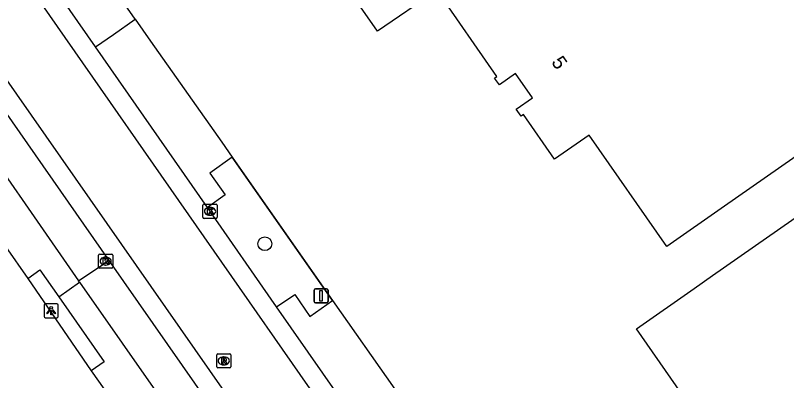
# Model space of a CAD drawing. Extents: x 156651 to 158072, y 387631 to 388990.
# Drawn here: x 157185.4 to 157240.2, y 388242.5 to 388268.5 of the extents above; entities that cross this region are included whole.
import ezdxf

# ---------------------------------------------------------------- set-up
doc = ezdxf.new("R2010")
doc.units = 0
for name, color, linetype in [('IMGEO_Berm_groen', 7, 'Continuous'), ('IMGEO_Boom', 7, 'Continuous'), ('IMGEO_Groenvoorziening', 7, 'Continuous'), ('IMGEO_Hek', 7, 'Continuous'), ('IMGEO_Kolk', 7, 'Continuous'), ('IMGEO_Lichtpunt', 7, 'Continuous'), ('IMGEO_Pand', 7, 'Continuous'), ('IMGEO_Pand_nummerreeks', 7, 'Continuous'), ('IMGEO_Rijbaan_lokaal_gesloten', 7, 'Continuous'), ('IMGEO_Rijbaan_lokaal_open', 7, 'Continuous'), ('IMGEO_Rioolput', 7, 'Continuous'), ('IMGEO_Verkeersbordpaal', 7, 'Continuous'), ('IMGEO_Voetpad_open', 7, 'Continuous')]:
    doc.layers.add(name, color=color, linetype=linetype)

msp = doc.modelspace()

# ---------------------------------------------------------------- linework, layer by layer
at = {"layer": 'IMGEO_Berm_groen'}
for points in [[(157193.882, 388268.245), (157172.367, 388299.009)], [(157207.925, 388248.229), (157200.786, 388258.42)]]:
    msp.add_lwpolyline(points, dxfattribs=at)
at = {"layer": 'IMGEO_Boom'}
msp.add_circle((157203.099, 388252.27), 0.489, dxfattribs=at)
at = {"layer": 'IMGEO_Groenvoorziening'}
msp.add_lwpolyline([(157186.236, 388249.801), (157190.75, 388243.22)], dxfattribs=at)
at = {"layer": 'IMGEO_Hek'}
for points in [[(157200.032, 388259.496), (157200.786, 388258.42)], [(157200.786, 388258.42), (157207.925, 388248.229)], [(157207.925, 388248.229), (157212.342, 388241.924)]]:
    msp.add_lwpolyline(points, dxfattribs=at)
at = {"layer": 'IMGEO_Kolk'}
for p, q in [((157198.7, 388254.146), (157198.7, 388254.998)), ((157198.775, 388255.072), (157199.627, 388255.072)), ((157199.188, 388254.852), (157199.213, 388254.852)), ((157199.701, 388254.998), (157199.701, 388254.146)), ((157199.211, 388254.292), (157199.186, 388254.292)), ((157199.627, 388254.072), (157198.775, 388254.072)), ((157191.276, 388250.605), (157191.276, 388251.457)), ((157191.351, 388251.531), (157192.203, 388251.531)), ((157192.277, 388251.457), (157192.277, 388250.605)), ((157191.764, 388251.311), (157191.789, 388251.311)), ((157192.203, 388250.531), (157191.351, 388250.531)), ((157191.787, 388250.751), (157191.762, 388250.751))]:
    msp.add_line(p, q, dxfattribs=at)
for points in [[(157198.7, 388254.146), (157198.7, 388254.998)], [(157198.775, 388255.072), (157199.627, 388255.072)], [(157199.021, 388254.772), (157199.144, 388254.772), (157199.144, 388254.621), (157199.274, 388254.772), (157199.438, 388254.772), (157199.292, 388254.621), (157199.445, 388254.372), (157199.293, 388254.372), (157199.208, 388254.536), (157199.144, 388254.469), (157199.144, 388254.372), (157199.021, 388254.372), (157199.021, 388254.772)], [(157199.701, 388254.998), (157199.701, 388254.146)], [(157199.627, 388254.072), (157198.775, 388254.072)], [(157191.276, 388250.605), (157191.276, 388251.457)], [(157191.351, 388251.531), (157192.203, 388251.531)], [(157192.277, 388251.457), (157192.277, 388250.605)], [(157191.597, 388251.231), (157191.72, 388251.231), (157191.72, 388251.08), (157191.85, 388251.231), (157192.014, 388251.231), (157191.868, 388251.08), (157192.021, 388250.831), (157191.869, 388250.831), (157191.784, 388250.995), (157191.72, 388250.928), (157191.72, 388250.831), (157191.597, 388250.831), (157191.597, 388251.231)], [(157192.203, 388250.531), (157191.351, 388250.531)]]:
    msp.add_lwpolyline(points, dxfattribs=at)
for centre, start, end in [((157198.777, 388254.996), 91.552, 178.448), ((157198.777, 388254.996), 91.552, 178.448), ((157199.625, 388254.996), 1.552, 88.448), ((157199.625, 388254.996), 1.552, 88.448), ((157198.777, 388254.148), 181.552, 268.448), ((157198.777, 388254.148), 181.552, 268.448), ((157199.625, 388254.148), 271.552, 358.448), ((157199.625, 388254.148), 271.552, 358.448), ((157191.353, 388251.455), 91.552, 178.448), ((157191.353, 388251.455), 91.552, 178.448), ((157192.201, 388251.455), 1.552, 88.448), ((157192.201, 388251.455), 1.552, 88.448), ((157191.353, 388250.607), 181.552, 268.448), ((157191.353, 388250.607), 181.552, 268.448), ((157192.201, 388250.607), 271.552, 358.448), ((157192.201, 388250.607), 271.552, 358.448)]:
    msp.add_arc(centre, 0.0765, start, end, dxfattribs=at)
for centre, major_axis, ratio, start_param, end_param in [((157199.187, 388254.572), (-0.387, 0.002), 0.722429, 4.712389, 7.853982), ((157199.212, 388254.572), (-0.39, 0.002), 0.717154, 1.570796, 4.712389), ((157191.763, 388251.031), (-0.387, 0.002), 0.722429, 4.712389, 7.853982), ((157191.788, 388251.031), (-0.39, 0.002), 0.717154, 1.570796, 4.712389)]:
    msp.add_ellipse(centre, major_axis=major_axis, ratio=ratio, start_param=start_param, end_param=end_param, dxfattribs=at)
at = {"layer": 'IMGEO_Lichtpunt'}
for p, q in [((157187.398, 388247.907), (157187.398, 388247.1)), ((157187.398, 388247.907), (157187.398, 388247.1)), ((157188.3, 388248.002), (157187.492, 388248.002)), ((157188.3, 388248.002), (157187.492, 388248.002)), ((157188.394, 388247.1), (157188.394, 388247.907)), ((157188.394, 388247.1), (157188.394, 388247.907)), ((157187.492, 388247.006), (157188.3, 388247.006)), ((157187.492, 388247.006), (157188.3, 388247.006))]:
    msp.add_line(p, q, dxfattribs=at)
for points in [[(157187.772, 388247.571), (157187.811, 388247.543), (157187.623, 388247.281), (157187.585, 388247.308), (157187.772, 388247.571)], [(157187.874, 388247.523), (157187.921, 388247.523), (157187.921, 388247.201), (157187.874, 388247.201), (157187.874, 388247.523)], [(157187.984, 388247.543), (157188.022, 388247.57), (157188.209, 388247.308), (157188.17, 388247.28), (157187.984, 388247.543)]]:
    msp.add_lwpolyline(points, dxfattribs=at)
msp.add_circle((157187.897, 388247.705), 0.0994, dxfattribs=at)
for centre, start, end in [((157187.492, 388247.907), 90, 180), ((157187.492, 388247.907), 90, 180), ((157188.3, 388247.907), 0, 90), ((157188.3, 388247.907), 0, 90), ((157187.492, 388247.1), 180, 270), ((157187.492, 388247.1), 180, 270), ((157188.3, 388247.1), 270, 0), ((157188.3, 388247.1), 270, 360)]:
    msp.add_arc(centre, 0.0946, start, end, dxfattribs=at)
at = {"layer": 'IMGEO_Pand'}
for points in [[(157224.658, 388276.883), (157252.506, 388296.33), (157266.462, 388276.354), (157235.802, 388254.933), (157231.703, 388252.069), (157226.167, 388259.993), (157223.715, 388258.28), (157221.495, 388261.458), (157221.333, 388261.345), (157220.992, 388261.833), (157222.145, 388262.639), (157220.935, 388264.371), (157219.786, 388263.574), (157219.437, 388264.047), (157219.61, 388264.167), (157215.353, 388270.292)], [(157215.353, 388270.292), (157211.106, 388267.393), (157202.392, 388279.88), (157198.304, 388277.05), (157196.864, 388279.117), (157194.804, 388277.677), (157189.199, 388285.691)], [(157263.552, 388245.577), (157261.548, 388248.448), (157239.235, 388232.876), (157239.531, 388232.452), (157234.785, 388229.139), (157230.685, 388226.277), (157227.61, 388230.684), (157231.638, 388233.495), (157231.013, 388234.39), (157235.57, 388237.57), (157229.534, 388246.219), (157233.635, 388249.081), (157234.952, 388250), (157252.108, 388261.974), (157258.657, 388266.545)]]:
    msp.add_lwpolyline(points, dxfattribs=at)
at = {"layer": 'IMGEO_Rijbaan_lokaal_gesloten'}
for points in [[(157341.899, 388076.038), (157340.456, 388076.982), (157309.901, 388101.717), (157302.391, 388108.413), (157297.417, 388113.326), (157292.839, 388118.359), (157292.715, 388118.524), (157290.068, 388122.059), (157284.128, 388130.537), (157250.785, 388178.4), (157218.017, 388225.194), (157168.536, 388296.106), (157166.328, 388299.54), (157165.346, 388302.72), (157165.232, 388304.849), (157165.572, 388307.171), (157166.44, 388309.461), (157166.862, 388310.136)], [(157159.256, 388297.816), (157160.307, 388298.772), (157166.301, 388290.299), (157236.347, 388190.018), (157288.771, 388114.767), (157287.657, 388113.917)], [(157191.042, 388266.266), (157169.573, 388297.067)], [(157199.027, 388254.836), (157191.042, 388266.266)], [(157183.303, 388263.514), (157191.992, 388251.074)], [(157203.933, 388247.771), (157199.027, 388254.836)], [(157191.992, 388251.074), (157225.926, 388202.493)], [(157210.521, 388238.352), (157203.933, 388247.771)]]:
    msp.add_lwpolyline(points, dxfattribs=at)
at = {"layer": 'IMGEO_Rijbaan_lokaal_open'}
for points in [[(157191.042, 388266.266), (157192.324, 388267.155), (157193.882, 388268.245)], [(157193.882, 388268.245), (157194.975, 388266.682), (157200.032, 388259.496), (157200.786, 388258.42)], [(157200.786, 388258.42), (157199.182, 388257.281), (157200.289, 388255.738), (157199.027, 388254.836)], [(157203.933, 388247.771), (157205.223, 388248.651), (157206.307, 388247.099), (157207.925, 388248.229)], [(157207.925, 388248.229), (157212.342, 388241.924)]]:
    msp.add_lwpolyline(points, dxfattribs=at)
at = {"layer": 'IMGEO_Rioolput'}
for p, q in [((157199.677, 388243.505), (157199.677, 388244.357)), ((157199.752, 388244.431), (157200.604, 388244.431)), ((157200.678, 388244.357), (157200.678, 388243.505)), ((157200.165, 388244.211), (157200.19, 388244.211)), ((157200.604, 388243.431), (157199.752, 388243.431)), ((157200.188, 388243.651), (157200.163, 388243.651))]:
    msp.add_line(p, q, dxfattribs=at)
for points in [[(157199.677, 388243.505), (157199.677, 388244.357)], [(157199.752, 388244.431), (157200.604, 388244.431)], [(157200.678, 388244.357), (157200.678, 388243.505)], [(157200.266, 388244.129), (157200.014, 388244.131), (157200.014, 388243.731)], [(157200.014, 388243.731), (157200.138, 388243.731), (157200.138, 388243.893), (157200.149, 388243.893)], [(157200.192, 388244.05), (157200.138, 388244.05), (157200.138, 388243.969)], [(157200.138, 388243.969), (157200.19, 388243.969)], [(157200.196, 388243.864), (157200.267, 388243.731), (157200.407, 388243.731), (157200.342, 388243.857)], [(157200.604, 388243.431), (157199.752, 388243.431)]]:
    msp.add_lwpolyline(points, dxfattribs=at)
for centre, radius, start, end in [((157199.754, 388244.355), 0.0765, 91.552, 178.448), ((157199.754, 388244.355), 0.0765, 91.552, 178.448), ((157200.602, 388244.355), 0.0765, 1.552, 88.448), ((157200.602, 388244.355), 0.0765, 1.552, 88.448), ((157200.148, 388243.84), 0.0533, 26.0293, 88.6989), ((157200.174, 388244.158), 0.19, 274.7715, 282.9687), ((157200.198, 388243.954), 0.0964, 77.0061, 93.1865), ((157200.212, 388244.011), 0.0378, 276.6634, 79.6772), ((157200.265, 388244.019), 0.109, 350.3612, 89.416), ((157200.263, 388244.019), 0.112, 277.5842, 350.9817), ((157200.247, 388243.804), 0.108, 29.5134, 73.7905), ((157199.754, 388243.507), 0.0765, 181.552, 268.448), ((157199.754, 388243.507), 0.0765, 181.552, 268.448), ((157200.602, 388243.507), 0.0765, 271.552, 358.448), ((157200.602, 388243.507), 0.0765, 271.552, 358.448)]:
    msp.add_arc(centre, radius, start, end, dxfattribs=at)
for centre, major_axis, ratio, start_param, end_param in [((157200.164, 388243.931), (-0.387, 0.002), 0.722429, 4.712389, 7.853982), ((157200.189, 388243.931), (-0.39, 0.002), 0.717154, 1.570796, 4.712389)]:
    msp.add_ellipse(centre, major_axis=major_axis, ratio=ratio, start_param=start_param, end_param=end_param, dxfattribs=at)
at = {"layer": 'IMGEO_Verkeersbordpaal'}
for p, q in [((157206.604, 388248.162), (157206.604, 388248.962)), ((157206.604, 388248.962), (157206.604, 388248.162)), ((157206.704, 388249.062), (157207.494, 388249.062)), ((157207.494, 388249.062), (157206.704, 388249.062)), ((157207.594, 388248.962), (157207.594, 388248.162)), ((157207.594, 388248.162), (157207.594, 388248.962)), ((157207.494, 388248.062), (157206.704, 388248.062)), ((157206.704, 388248.062), (157207.494, 388248.062))]:
    msp.add_line(p, q, dxfattribs=at)
msp.add_lwpolyline([(157207.024, 388248.937), (157207.174, 388248.937), (157207.174, 388248.187), (157207.024, 388248.187), (157207.024, 388248.937)], dxfattribs=at)
for centre, start, end in [((157206.704, 388248.962), 90, 180), ((157206.704, 388248.962), 90, 180), ((157207.494, 388248.962), 0, 90), ((157207.494, 388248.962), 360, 90), ((157206.704, 388248.162), 180, 270), ((157206.704, 388248.162), 180, 270), ((157207.494, 388248.162), 270, 0), ((157207.494, 388248.162), 270, 0)]:
    msp.add_arc(centre, 0.1, start, end, dxfattribs=at)
at = {"layer": 'IMGEO_Voetpad_open'}
for points in [[(157181.211, 388262.053), (157189.849, 388249.638)], [(157179.863, 388258.901), (157186.236, 388249.801)], [(157189.849, 388249.638), (157191.992, 388251.074)], [(157186.236, 388249.801), (157187.096, 388250.405), (157188.446, 388248.5)], [(157188.446, 388248.5), (157189.923, 388249.531)], [(157189.923, 388249.531), (157189.849, 388249.638)], [(157189.923, 388249.531), (157223.628, 388201.343)], [(157188.446, 388248.5), (157191.668, 388243.863), (157190.75, 388243.22)], [(157190.75, 388243.22), (157192.467, 388240.777)]]:
    msp.add_lwpolyline(points, dxfattribs=at)

# ---------------------------------------------------------------- texts
at = {"layer": 'IMGEO_Pand_nummerreeks'}
msp.add_text('5', height=1, rotation=304.9387, dxfattribs=at).set_placement((157223.447, 388265.175))

doc.saveas('drawing.dxf')
